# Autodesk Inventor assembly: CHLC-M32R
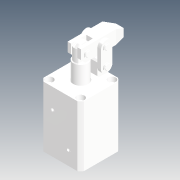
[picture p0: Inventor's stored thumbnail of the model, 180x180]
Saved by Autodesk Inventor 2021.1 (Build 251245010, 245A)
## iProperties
Company: Microsoft
Created: 2019-11
Part Number: CHLC-M32R
Description: STEP AP214
Document SubType Name: Assembly
Designer: user
Title: CHLC-M32R.STEP
Author: Windows
Revision Number: ÈÎºÎ
Sending System: SolidWorks 2015
Preprocessor: SwSTEP 2.0
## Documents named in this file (10)
- D:\Vault_2016\Projekty\Clamptek\Hydraulic\CHLC\CHLC-32\Inventor\CHLC-M32R\CHLC-M32R.iam
- D:\Vault_2016\Projekty\Clamptek\Hydraulic\CHLC\CHLC-32\Inventor\CHLC-M32R\CHLC-M32-±¾Ìå.ipt
- D:\Vault_2016\Projekty\Clamptek\Hydraulic\CHLC\CHLC-32\Inventor\CHLC-M32R\CHLC-M32-͹̨.ipt
- D:\Vault_2016\Projekty\Clamptek\Hydraulic\CHLC\CHLC-32\Inventor\CHLC-M32R\CHLC-32-02_1.ipt
- D:\Vault_2016\Projekty\Clamptek\Hydraulic\CHLC\CHLC-32\Inventor\CHLC-M32R\CHLC-32-03_1.ipt
- D:\Vault_2016\Projekty\Clamptek\Hydraulic\CHLC\CHLC-32\Inventor\CHLC-M32R\CHLC-32-04_1.ipt
- D:\Vault_2016\Projekty\Clamptek\Hydraulic\CHLC\CHLC-32\Inventor\CHLC-M32R\CHLC-32-08_1.ipt
- D:\Vault_2016\Projekty\Clamptek\Hydraulic\CHLC\CHLC-32\Inventor\CHLC-M32R\LHC01D-32-01_1.ipt
- D:\Vault_2016\Projekty\Clamptek\Hydraulic\CHLC\CHLC-32\Inventor\CHLC-M32R\M6LS.ipt
- D:\Vault_2016\Projekty\Clamptek\Hydraulic\CHLC\CHLC-32\Inventor\CHLC-M32R\Ñ¹±Û.ipt
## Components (17 placed, 17 different names)
1. CHLC-M32-±¾Ìå_1
2. CHLC-M32-͹̨_2
3. CHLC-32-02_1_3
4. CHLC-32-03_1_4
5. CHLC-32-04_1_5
6. CHLC-32-08_1_6
7. LHC01D-32-01_1_7
8. CHLC-32-03_1_8
9. LHC01D-32-01_1_9
10. LHC01D-32-01_1_10
11. CHLC-32-04_1_11
12. LHC01D-32-01_1_12
13. LHC01D-32-01_1_13
14. LHC01D-32-01_1_14
15. M6LS_15
16. M6LS_16
17. Ñ¹±Û_17
